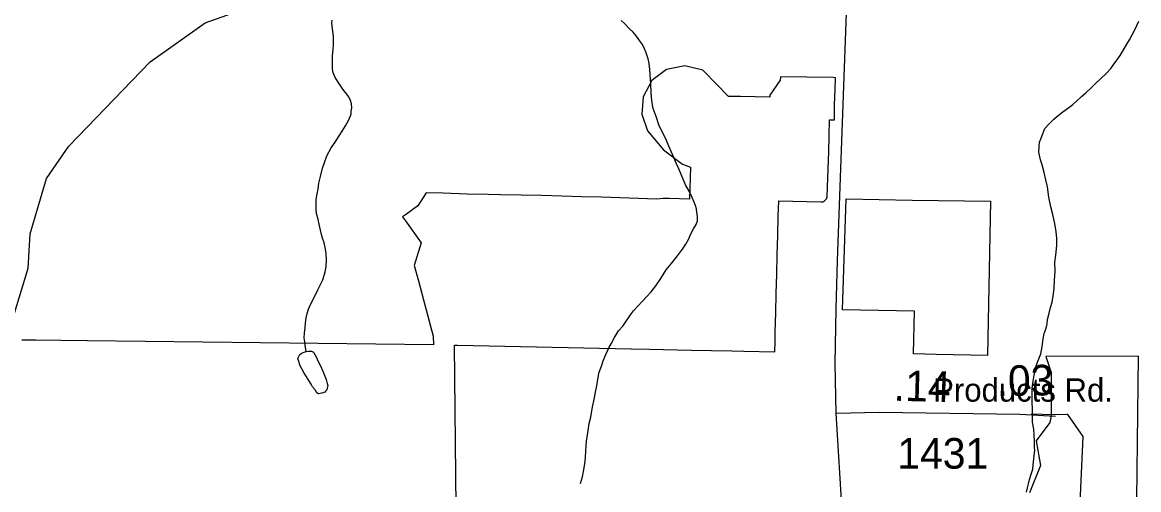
# Model space of a CAD drawing. Extents: x 2001466 to 2224147, y 644118 to 847247.
# Drawn here: x 2063724 to 2068284, y 672391 to 674300 of the extents above; entities that cross this region are included whole.
import ezdxf

# ---------------------------------------------------------------- set-up
doc = ezdxf.new("R2010")
doc.units = 0
for name, color, linetype in [('Exist Boundary Political City Limit New', 7, 'Continuous'), ('Exist Hydrographic Creek Single Shore', 7, 'Continuous'), ('Exist Hydrographic Misc Water Feature', 7, 'Continuous'), ('Exist Road Non-System Type 51', 7, 'Continuous'), ('Exist Road Secondary Mileage Hundredths English Label', 7, 'Continuous'), ('Exist Road Secondary Type 51 Attributed', 7, 'Continuous'), ('Exist Road Secondary Type 51 Label', 7, 'Continuous'), ('Exist Road Secondary Type 51 Number Label', 7, 'Continuous'), ('Map Preparation Boundary City Limit Buffer Line', 7, 'Continuous')]:
    doc.layers.add(name, color=color, linetype=linetype)

msp = doc.modelspace()

# ---------------------------------------------------------------- linework, layer by layer
at = {"layer": 'Exist Boundary Political City Limit New'}
for points in [[(2067018.1, 673771.6), (2067022.1, 673902.2), (2067042.1, 673901.6), (2067042.2, 673962.6), (2067044.4, 674026.3), (2067046.2, 674073.5), (2067036.2, 674073.9), (2066820.9, 674077.6), (2066820.6, 674063.9), (2066778.4, 674001.9), (2066778.4, 673994.1), (2066658.4, 673996.4), (2066608.4, 673997.4), (2066562, 674045.1), (2066503.6, 674105.1), (2066430, 674122.2), (2066356, 674106.6), (2066295.9, 674061.6), (2066260.1, 673995.7), (2066254.8, 673924.3), (2066278.5, 673856.7), (2066342.9, 673778.8), (2066421.5, 673720.3), (2066453.1, 673708.4), (2066450, 673578.1), (2066367, 673579.9), (2066342.5, 673579.8), (2066315.6, 673577.9), (2066090.6, 673586.3), (2066008.5, 673587.7), (2065928.4, 673590), (2065845.5, 673591.9), (2065762.5, 673593.8), (2065677.6, 673595.4), (2065627.6, 673596.6), (2065541.8, 673598.6), (2065443, 673601.5), (2065374.2, 673603.2), (2065339.5, 673550.3), (2065293.2, 673517), (2065277, 673505.3), (2065288.8, 673489.1), (2065353, 673399.8), (2065325.5, 673306.1), (2065342.1, 673244.1), (2065363, 673166.3), (2065402.8, 673018.3), (2065403.2, 672982.6), (2063990.9, 672999.5), (2063881.2, 673000.3), (2063779.2, 673001.1), (2063721.5, 673001.5)], [(2065496.6, 672319.8), (2065489.2, 672981.5), (2065501.9, 672981.3), (2066210.8, 672966.5), (2066285.6, 672964.9), (2066457.4, 672961.2), (2066539.8, 672959.5), (2066622, 672957.8), (2066671.4, 672956.7), (2066798.6, 672953.9), (2066799.2, 672994.9), (2066800.1, 673034.9), (2066802.1, 673113.8), (2066804, 673192.8), (2066805.9, 673271.8), (2066807.8, 673350.8), (2066809.8, 673429.8), (2066811.6, 673509.8), (2066814.2, 673570.2), (2066986, 673566.3), (2066989.9, 673566.5), (2066993.8, 673567.2), (2066997.5, 673568.6), (2067000.9, 673570.6), (2067003.9, 673573), (2067006.6, 673575.9), (2067008.8, 673579.2), (2067010.4, 673582.8), (2067011.4, 673586.6), (2067011.9, 673590.4), (2067016.9, 673737.2), (2067018.1, 673771.6)], [(2067679.2, 673569.3), (2067667.6, 672939.3), (2067457.1, 672943.4), (2067364.2, 672945.7), (2067368.8, 673120.2), (2067074.2, 673126.2), (2067089.4, 673579.3), (2067359.2, 673573.5), (2067679.2, 673569.3)], [(2068275.2, 672234.5), (2068284, 672935.8), (2067905.8, 672934.5), (2067926.9, 672869.2), (2067926.9, 672726), (2067926.9, 672692.7), (2067921.2, 672666.1), (2067866.1, 672591.2), (2067883.5, 672490.1), (2067839, 672378.1)]]:
    msp.add_lwpolyline(points, dxfattribs=at)
at = {"layer": 'Exist Hydrographic Creek Single Shore'}
msp.add_lwpolyline([(2063674.4, 672967.6), (2063665.5, 673021.7), (2063748.3, 673295.6), (2063756.3, 673436.6), (2063822.4, 673661.6), (2063914.4, 673794.2), (2064246.4, 674138.6), (2064471.3, 674298), (2064987.5, 674481), (2065245.4, 674666.1), (2065362.5, 674841), (2065453.5, 675049.1), (2065461.5, 675163.7)], dxfattribs=at)
at = {"layer": 'Exist Hydrographic Misc Water Feature'}
for points in [[(2064883.7, 672954.8), (2064879.6, 672981), (2064877.8, 672995), (2064875.3, 673010.8), (2064877.3, 673030.8), (2064879.4, 673052.8), (2064881.5, 673072.8), (2064883.5, 673092.7), (2064887.2, 673110.8), (2064893.3, 673129), (2064901.3, 673146.8), (2064913, 673171), (2064930.9, 673206.8), (2064941.1, 673226.8), (2064951.2, 673248.8), (2064961, 673280.9), (2064964.9, 673303.1), (2064967, 673329.1), (2064964.9, 673357), (2064960.8, 673380.7), (2064956.5, 673398.8), (2064951, 673418.7), (2064946.9, 673432.8), (2064942.8, 673450.8), (2064936.4, 673474.9), (2064932.5, 673495), (2064926.4, 673519), (2064924.7, 673536.7), (2064924.3, 673555), (2064924.5, 673576.9), (2064928.2, 673599), (2064932.3, 673618.7), (2064936, 673642.9), (2064942.4, 673670.7), (2064950.1, 673704.8), (2064958.1, 673726.7), (2064968.2, 673754.8), (2064986, 673787), (2065001.8, 673810.9), (2065018, 673836.9), (2065030.1, 673854.9), (2065043.9, 673877.2), (2065057.6, 673901.1), (2065067.6, 673925.1), (2065068, 673937.2), (2065069.9, 673951.1), (2065069.5, 673967), (2065065.4, 673981), (2065059.8, 673993.2), (2065049.4, 674007), (2065037.7, 674020.9), (2065027.7, 674035), (2065019.7, 674047.2), (2065001.6, 674075), (2064993.6, 674092.9), (2064991.6, 674109), (2064991.4, 674122.8), (2064991.4, 674142.7), (2064991.4, 674163), (2064993.6, 674187), (2064995, 674209), (2064995.3, 674224.8), (2064995.3, 674242.7), (2064993, 674262.9), (2064991.2, 674274.9), (2064988.9, 674294.8), (2064989.3, 674308.9)], [(2066004.3, 672417), (2066012.5, 672443), (2066016.2, 672465.2), (2066022.4, 672497.1), (2066024.2, 672521.1), (2066026.3, 672551.3), (2066028.3, 672589), (2066033.8, 672623.1), (2066039.8, 672661.1), (2066045.9, 672687), (2066053.7, 672729.2), (2066059.7, 672759.1), (2066065.4, 672789.1), (2066071.6, 672815.3), (2066075.3, 672843.1), (2066081.2, 672871), (2066089.6, 672895.3), (2066097.4, 672917.2), (2066107.3, 672943.3), (2066115.5, 672961.1), (2066121.2, 672973.2), (2066129, 672987.1), (2066143.1, 673013.3), (2066158.9, 673039.3), (2066177.2, 673059.3), (2066209.2, 673105.1), (2066221.1, 673121.2), (2066256.7, 673159.5), (2066275, 673179.5), (2066292.8, 673199.5), (2066312.5, 673223.3), (2066332.8, 673253.5), (2066354.5, 673289.5), (2066374.8, 673313.6), (2066400.5, 673345.8), (2066420.4, 673373.7), (2066434.5, 673393.9), (2066446.6, 673415.5), (2066454.2, 673433.8), (2066466.5, 673455.9), (2066476.3, 673473.9), (2066482.3, 673489.6), (2066482.3, 673507.9), (2066480.2, 673523.6), (2066478.4, 673537.7), (2066473.9, 673551.7), (2066460.1, 673583.8), (2066447.8, 673609.6), (2066433.9, 673635.7), (2066423.9, 673659.5), (2066415.9, 673677.7), (2066405.8, 673701.5), (2066396, 673721.7), (2066385.9, 673747.6), (2066375.9, 673769.4), (2066365.8, 673793.6), (2066355.8, 673817.4), (2066343.7, 673843.2), (2066325.4, 673877.6), (2066313.5, 673915.5), (2066301.4, 673947.3), (2066295.3, 673979.1), (2066293.2, 674013.5), (2066291.4, 674047.5), (2066287.3, 674107.3), (2066285.2, 674131.1), (2066280.9, 674151.2), (2066273.1, 674175.2), (2066265.1, 674191.4), (2066257.1, 674209.2), (2066244.8, 674225.2), (2066232.9, 674243.3), (2066219, 674259.2), (2066203, 674275), (2066184.8, 674293.2), (2066171, 674307)], [(2067942.3, 673318.6), (2067946, 673348.4), (2067950.1, 673388.4), (2067950.1, 673418.4), (2067948, 673444.7), (2067942.1, 673478.4), (2067933.7, 673514.6), (2067925.9, 673546.6), (2067918.1, 673586.3), (2067911.9, 673628.2), (2067905.6, 673656.4), (2067897.8, 673686.3), (2067889.6, 673718.4), (2067883.4, 673738.4), (2067877.3, 673770.1), (2067877.7, 673792.4), (2067879.3, 673810.4), (2067885.5, 673826.5), (2067891.4, 673842.2), (2067901.5, 673866.2), (2067917, 673884.2), (2067925.2, 673892.2), (2067937.5, 673904.2), (2067949.2, 673914.2), (2067975.3, 673934.6), (2067999.1, 673952.5), (2068015.1, 673964.6), (2068031.1, 673978.5), (2068050.9, 673996.5), (2068069, 674012.5), (2068089.1, 674030.5), (2068106.9, 674048.5), (2068128.9, 674068.6), (2068152.9, 674092.6), (2068170.7, 674110.6), (2068180.7, 674124.9), (2068194.7, 674144.7), (2068208.8, 674164.9), (2068220.5, 674185), (2068236.7, 674210.9), (2068246.6, 674228.9), (2068258.5, 674249), (2068268.5, 674268.9), (2068276.7, 674286.8), (2068284.5, 674305.1)], [(2067826, 672380.6), (2067829.7, 672398.3), (2067834.2, 672414.7), (2067837.9, 672432.4), (2067845.9, 672454.7), (2067851.8, 672474.5), (2067853.5, 672492.5), (2067855.7, 672516.5), (2067857.6, 672530.4), (2067859.8, 672550.7), (2067859.4, 672566.6), (2067859.6, 672590.5), (2067857.6, 672614.4), (2067855.7, 672638.6), (2067851.4, 672666.4), (2067851.2, 672698.5), (2067851.4, 672720.3), (2067849.4, 672748.6), (2067849.2, 672778.2), (2067849.2, 672806.2), (2067853.1, 672834.5), (2067857.2, 672858.6), (2067862.9, 672888.5), (2067870.7, 672912.5), (2067884.8, 672946.4), (2067890.8, 672976.4), (2067894.9, 673006.6), (2067898.6, 673028.7), (2067907, 673050.6), (2067910.9, 673068.6), (2067912.5, 673086.6), (2067918.5, 673112.5), (2067924.8, 673134.7), (2067930.6, 673156.5), (2067936.7, 673190.5), (2067938.6, 673214.5), (2067940.4, 673246.7), (2067942.7, 673282.5), (2067942.3, 673318.6)], [(2064883.7, 672954.8), (2064893.5, 672956.9), (2064905.9, 672956.7), (2064913.6, 672953.1), (2064919.6, 672942.8), (2064925.7, 672931), (2064931.5, 672917.1), (2064941.7, 672896.9), (2064951.8, 672875.1), (2064959.8, 672855.2), (2064965.5, 672841), (2064969.6, 672824.9), (2064971.7, 672816.9), (2064969.8, 672805.1), (2064968, 672799.3), (2064963.9, 672795), (2064960, 672789.1), (2064947.7, 672785.3), (2064933.7, 672783), (2064927.6, 672787.1), (2064919.8, 672798.9), (2064910, 672810.9), (2064903.8, 672822.7), (2064894, 672836.8), (2064889.7, 672844.8), (2064883.7, 672855), (2064875.5, 672866.8), (2064865.9, 672884.9), (2064859.7, 672896.8), (2064851.9, 672918.7), (2064849.9, 672926.7), (2064851.7, 672932.9), (2064857.7, 672943), (2064863.8, 672946.8), (2064871.6, 672950.9), (2064883.7, 672954.8)]]:
    msp.add_lwpolyline(points, dxfattribs=at)
at = {"layer": 'Exist Road Non-System Type 51'}
msp.add_lwpolyline([(2067678, 671530.8), (2067809.4, 671527.8), (2067923.4, 671527.4), (2067961.5, 671532.7), (2067975.5, 671532.4), (2067993.8, 671546), (2068000, 671557.9), (2068008.5, 671579.7), (2068013.2, 671615.6), (2068057.4, 672608.7), (2067994.8, 672697.6), (2067991.2, 672698.1), (2067939.2, 672697.1), (2067845.6, 672699.7)], dxfattribs=at)
at = {"layer": 'Exist Road Secondary Type 51 Attributed'}
for points in [[(2067210.1, 676036.8), (2067218.9, 675987.6), (2067229.9, 675881.7), (2067226.9, 675628.6), (2067210.4, 675490.1), (2067176.5, 675344.5), (2067119.7, 675121.8), (2067095.2, 674787.5), (2067090.5, 674375.3), (2067061.3, 673553), (2067052.6, 673326.4), (2067047.9, 673130.2), (2067043.2, 672906), (2067047.9, 672703.9)], [(2067047.9, 672703.9), (2067226.2, 672707.9), (2067799, 672700), (2067945.2, 672691.9)], [(2067047.9, 672703.9), (2067073.2, 672281.5), (2067090.5, 671953.1), (2067112.6, 671623.8), (2067136.3, 671404.3), (2067189.3, 671087.7)]]:
    msp.add_lwpolyline(points, dxfattribs=at)
at = {"layer": 'Map Preparation Boundary City Limit Buffer Line'}
for points in [[(2067018.1, 673771.6), (2067022.1, 673902.2), (2067042.1, 673901.6), (2067042.2, 673962.6), (2067044.4, 674026.3), (2067046.2, 674073.5), (2067036.2, 674073.9), (2066820.9, 674077.6), (2066820.6, 674063.9), (2066778.4, 674001.9), (2066778.4, 673994.1), (2066658.4, 673996.4), (2066608.4, 673997.4), (2066562, 674045.1), (2066503.6, 674105.1), (2066430, 674122.2), (2066356, 674106.6), (2066295.9, 674061.6), (2066260.1, 673995.7), (2066254.8, 673924.3), (2066278.5, 673856.7), (2066342.9, 673778.8), (2066421.5, 673720.3), (2066453.1, 673708.4), (2066450, 673578.1), (2066367, 673579.9), (2066342.5, 673579.8), (2066315.6, 673577.9), (2066090.6, 673586.3), (2066008.5, 673587.7), (2065928.4, 673590), (2065845.5, 673591.9), (2065762.5, 673593.8), (2065677.6, 673595.4), (2065627.6, 673596.6), (2065541.8, 673598.6), (2065443, 673601.5), (2065374.2, 673603.2), (2065339.5, 673550.3), (2065293.2, 673517), (2065277, 673505.3), (2065288.8, 673489.1), (2065353, 673399.8), (2065325.5, 673306.1), (2065342.1, 673244.1), (2065363, 673166.3), (2065402.8, 673018.3), (2065403.2, 672982.6), (2063990.9, 672999.5), (2063881.2, 673000.3), (2063779.2, 673001.1), (2063721.5, 673001.5)], [(2065496.6, 672319.8), (2065489.2, 672981.5), (2065501.9, 672981.3), (2066210.8, 672966.5), (2066285.6, 672964.9), (2066457.4, 672961.2), (2066539.8, 672959.5), (2066622, 672957.8), (2066671.4, 672956.7), (2066798.6, 672953.9), (2066799.2, 672994.9), (2066800.1, 673034.9), (2066802.1, 673113.8), (2066804, 673192.8), (2066805.9, 673271.8), (2066807.8, 673350.8), (2066809.8, 673429.8), (2066811.6, 673509.8), (2066814.2, 673570.2), (2066986, 673566.3), (2066989.9, 673566.5), (2066993.8, 673567.2), (2066997.5, 673568.6), (2067000.9, 673570.6), (2067003.9, 673573), (2067006.6, 673575.9), (2067008.8, 673579.2), (2067010.4, 673582.8), (2067011.4, 673586.6), (2067011.9, 673590.4), (2067016.9, 673737.2), (2067018.1, 673771.6)], [(2067679.2, 673569.3), (2067667.6, 672939.3), (2067457.1, 672943.4), (2067364.2, 672945.7), (2067368.8, 673120.2), (2067074.2, 673126.2), (2067089.4, 673579.3), (2067359.2, 673573.5), (2067679.2, 673569.3)], [(2068275.2, 672234.5), (2068284, 672935.8), (2067905.8, 672934.5), (2067926.9, 672869.2), (2067926.9, 672726), (2067926.9, 672692.7), (2067921.2, 672666.1), (2067866.1, 672591.2), (2067883.5, 672490.1), (2067839, 672378.1)]]:
    msp.add_lwpolyline(points, dxfattribs=at)

# ---------------------------------------------------------------- texts
at = {"layer": 'Exist Road Secondary Mileage Hundredths English Label'}
for s, rotation, p in [('.03', 1.037, (2067705.1, 672772.6)), ('.14', 358.4479, (2067282.4, 672754.6))]:
    msp.add_text(s, height=125, rotation=rotation, dxfattribs=at).set_placement(p)
at = {"layer": 'Exist Road Secondary Type 51 Label'}
msp.add_text('Products Rd.', height=95, rotation=359.9944, dxfattribs=at).set_placement((2067445, 672750.7))
at = {"layer": 'Exist Road Secondary Type 51 Number Label'}
msp.add_text('1431', height=125, dxfattribs=at).set_placement((2067298.3, 672477))

doc.saveas('drawing.dxf')
